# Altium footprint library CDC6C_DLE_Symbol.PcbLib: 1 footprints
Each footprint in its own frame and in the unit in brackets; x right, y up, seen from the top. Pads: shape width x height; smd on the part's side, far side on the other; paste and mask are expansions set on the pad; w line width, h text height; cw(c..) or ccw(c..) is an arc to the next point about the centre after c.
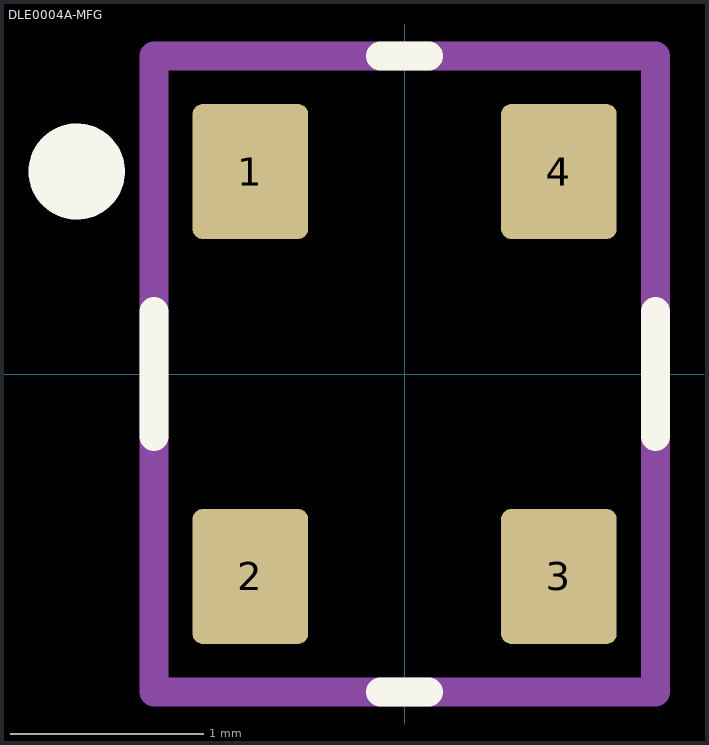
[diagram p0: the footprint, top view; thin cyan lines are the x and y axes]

## DLE0004A-MFG [mm]
pads (4):
  rrect17% 0.6x0.7 smd paste-1000 mask+0: 1(-0.8,1.05) 2(-0.8,-1.05) 3(0.8,-1.05) 4(0.8,1.05)
Top Overlay:
  circle w0.25: c-1.7,1.05 r0.125
  lines w0.15: -1.3,-0.325 -1.3,0.325 ; -0.125,-1.65 0.125,-1.65 ; -0.125,1.65 0.125,1.65 ; 1.3,-0.325 1.3,0.325
Top Paste:
  region: -0.5,-0.775 -0.5,-1.325 -0.5,-1.335 -0.508,-1.353 -0.522,-1.367 -0.54,-1.375 -0.55,-1.375 -1.05,-1.375 -1.06,-1.375 -1.078,-1.367 -1.092,-1.353 -1.1,-1.335 -1.1,-1.325 -1.1,-0.775 -1.1,-0.765 -1.092,-0.747 -1.078,-0.733 -1.06,-0.725 -1.05,-0.725 -0.55,-0.725 -0.54,-0.725 -0.522,-0.733 -0.508,-0.747 -0.5,-0.765
  region: 1.05,-0.725 1.06,-0.725 1.078,-0.733 1.092,-0.747 1.1,-0.765 1.1,-0.775 1.1,-1.325 1.1,-1.335 1.092,-1.353 1.078,-1.367 1.06,-1.375 1.05,-1.375 0.55,-1.375 0.54,-1.375 0.522,-1.367 0.508,-1.353 0.5,-1.335 0.5,-1.325 0.5,-0.775 0.5,-0.765 0.508,-0.747 0.522,-0.733 0.54,-0.725 0.55,-0.725
  region: 0.5,1.325 0.5,1.335 0.508,1.353 0.522,1.367 0.54,1.375 0.55,1.375 1.05,1.375 1.06,1.375 1.078,1.367 1.092,1.353 1.1,1.335 1.1,1.325 1.1,0.775 1.1,0.765 1.092,0.747 1.078,0.733 1.06,0.725 1.05,0.725 0.55,0.725 0.54,0.725 0.522,0.733 0.508,0.747 0.5,0.765 0.5,0.775
  region: -0.55,1.375 -0.54,1.375 -0.522,1.367 -0.508,1.353 -0.5,1.335 -0.5,1.325 -0.5,0.775 -0.5,0.765 -0.508,0.747 -0.522,0.733 -0.54,0.725 -0.55,0.725 -1.05,0.725 -1.06,0.725 -1.078,0.733 -1.092,0.747 -1.1,0.765 -1.1,0.775 -1.1,1.325 -1.1,1.335 -1.092,1.353 -1.078,1.367 -1.06,1.375 -1.05,1.375
Mechanical 5:
  lines w0.15: -1.3,-1.65 -1.3,1.65 1.3,1.65 1.3,-1.65 -1.3,-1.65
  text ".Designator" at 0.05,0.217 h0.5
3D body "Crys_CDC6CXXXXXXXDLET_VSON4.STEP": height 0.25, standoff 0, extent -1.4,-1.75 1.4,1.75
